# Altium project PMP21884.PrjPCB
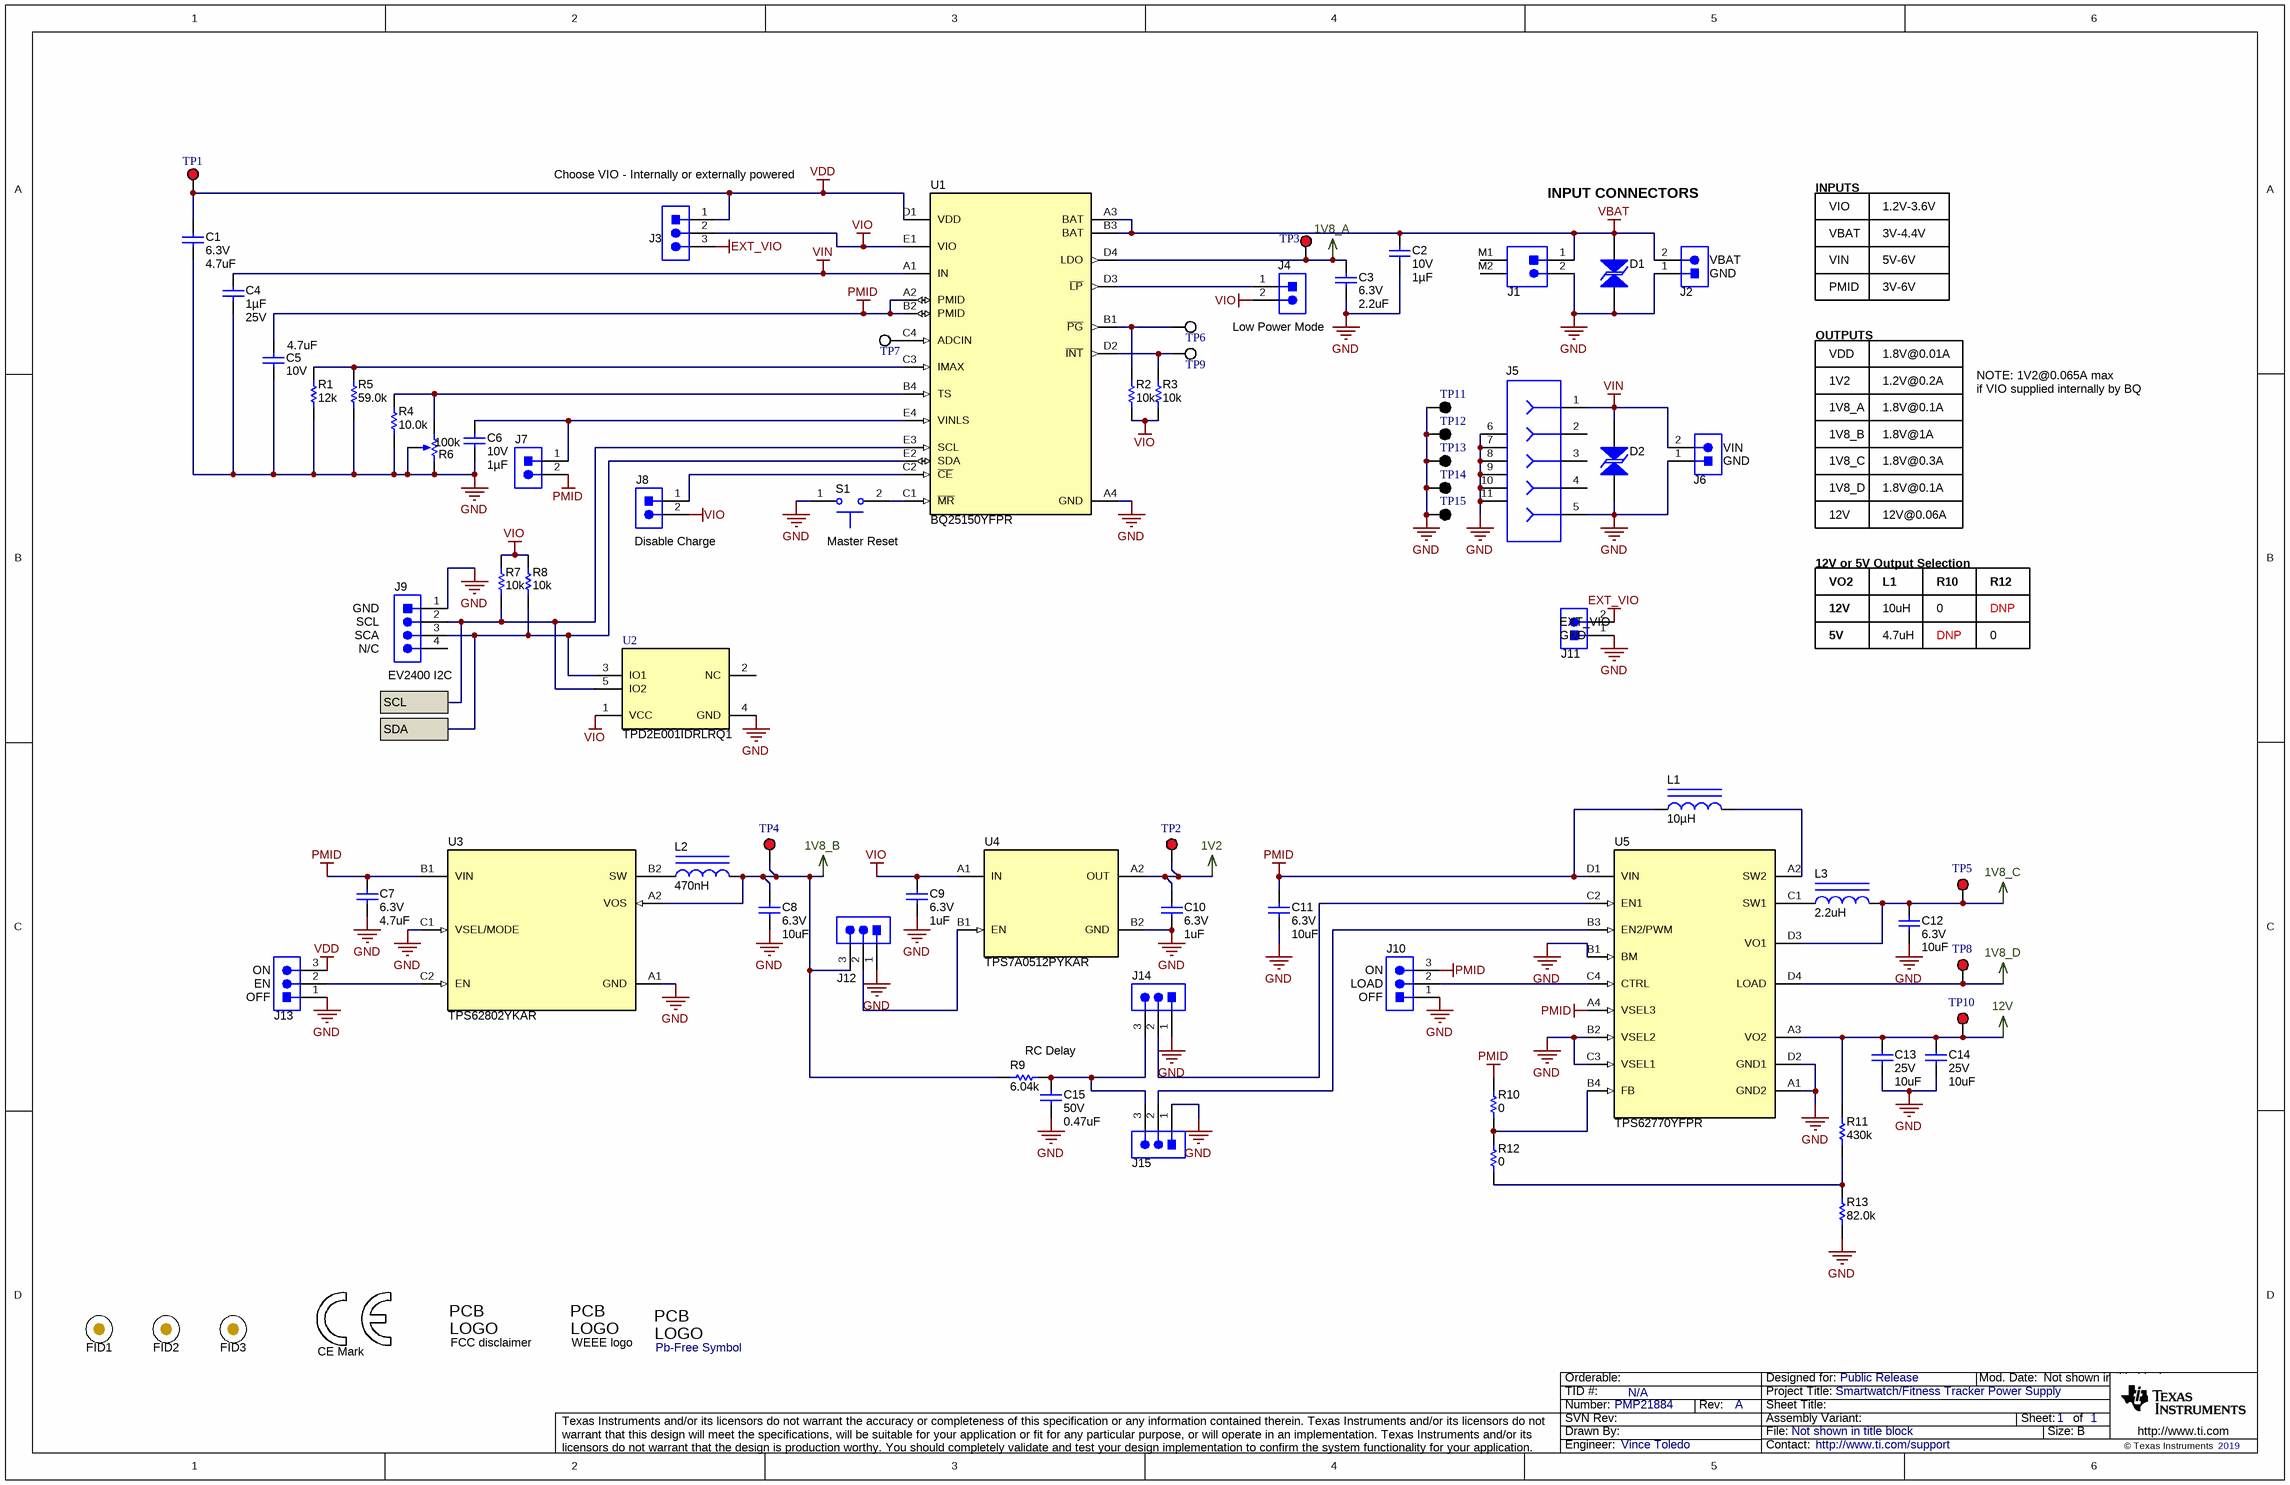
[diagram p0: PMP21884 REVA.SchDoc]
TID: N/A; TechSupport: http://www.ti.com/support; SCH_Rev: A; PRJ_Title: Smartwatch/Fitness Tracker Power Supply; PRJ_Number: PMP21884; PRJ_Engineer: Vince Toledo; PRJ_Customer: Public Release; PCB_Rev: A; PCB_Layout: Vince Toledo; CopyrightYear: 2019
1 sheet, 76 parts. Net scope: flat (ports and power ports of the same name join across sheets).
Board file: PMP21884 REVA PCB.PcbDoc

## Sheet PMP21884 REVA.SchDoc
size 431 x 279 mm; Date: Not shown in title block; ApprovedBy: Not shown in title block; CheckedBy: Not shown in title block; Author: Not shown in title block; CompanyName: Not shown in title block; Engineer: Not shown in title block; Organization: Not shown in title block; Address1: Not shown in title block; Address2: Not shown in title block; Address3: Not shown in title block; Address4: Not shown in title block; DocumentNumber: 1; Revision: Use project parameter SCH_Rev; SheetNumber: 1; SheetTotal: 1; PageSetup: Record=PageOptions¦CenterHorizontal=True¦CenterVertical=True¦PrintScale=1.00¦XCorrection=1.00¦YCorrection=1.00¦PrintKind=0¦BorderSize=5000000¦LeftOffset=0¦BottomOffset=0¦Orientation=2¦PaperLength=1000¦PaperWidth=1000¦Scale=100¦PaperSource=15¦PrintQuality=600¦MediaType=1¦DitherType=10¦PaperKind=Letter¦PrintScaleMode=1

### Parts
C1  VDC_V: 6.3V  ValueDisplayed: 4.7uF  [0201L]  (hidden comment: GRM035R60J475ME15D)
C2  VDC_V: 10V  ValueDisplayed: 1µF  [0402S]  (hidden comment: CL05A105MP5NNNC)
C3  VDC_V: 6.3V  ValueDisplayed: 2.2uF  [0201L]  (hidden comment: CL03A225MQ3CRNC)
C4  ValueDisplayed: 1µF  VDC_V: 25V  [0402S]  (hidden comment: CL05A105KA5NQNC)
C5  VDC_V: 10V  ValueDisplayed: 4.7uF  [0402S]  (hidden comment: C1005X5R1A475M050BC)
C6  VDC_V: 10V  ValueDisplayed: 1µF  [0402S]  (hidden comment: CL05A105MP5NNNC)
C7  VDC_V: 6.3V  ValueDisplayed: 4.7uF  [0201L]  (hidden comment: GRM035R60J475ME15D)
C8  VDC_V: 6.3V  ValueDisplayed: 10uF  [0402S]  (hidden comment: GRM155R60J106ME15D)
C9  VDC_V: 6.3V  ValueDisplayed: 1uF  [0201_033L]  (hidden comment: GRM033R60J105MEA2D)
C10  VDC_V: 6.3V  ValueDisplayed: 1uF  [0201_033L]  (hidden comment: GRM033R60J105MEA2D)
C11  VDC_V: 6.3V  ValueDisplayed: 10uF  [0402S]  (hidden comment: GRM155R60J106ME15D)
C12  VDC_V: 6.3V  ValueDisplayed: 10uF  [0402S]  (hidden comment: GRM155R60J106ME15D)
C13  VDC_V: 25V  ValueDisplayed: 10uF  [0603S]  (hidden comment: GRM188R61E106MA73J)
C14  VDC_V: 25V  ValueDisplayed: 10uF  [0603S]  (hidden comment: GRM188R61E106MA73J)
C15  VDC_V: 50V  ValueDisplayed: 0.47uF  [1206_190]  (hidden comment: CGA5L2X5R1H474K160AA)
D1  TPD1E6B06DPLR  [DPL0002A]  (value not drawn)
D2  TPD1E6B06DPLR  [DPL0002A]  (value not drawn)
FID1  Fiducial  [Fiducial10-20]  (value not drawn)
FID2  Fiducial  [Fiducial10-20]  (value not drawn)
FID3  Fiducial  [Fiducial10-20]  (value not drawn)
J1  S2B-PH-SM4-TB(LF)(SN)  [JST_S2B-PH-SM4-TB]  (value not drawn)
J2  PEC02SAAN  [CONN_PEC02SAAN]  (value not drawn)
J3  PEC03SAAN  [CONN_PEC03SAAN]  (value not drawn)
J4  PEC02SAAN  [CONN_PEC02SAAN]  (value not drawn)
J5  105017-0001  [CONN_105017-0001]  (value not drawn)
J6  PEC02SAAN  [CONN_PEC02SAAN]  (value not drawn)
J7  PEC02SAAN  [CONN_PEC02SAAN]  (value not drawn)
J8  PEC02SAAN  [CONN_PEC02SAAN]  (value not drawn)
J9  22/05/3041  [CONN_22-05-3041]  (value not drawn)
J10  PEC03SAAN  [CONN_PEC03SAAN]  (value not drawn)
J11  PEC02SAAN  [CONN_PEC02SAAN]  (value not drawn)
J12  PEC03SAAN  [CONN_PEC03SAAN]  (value not drawn)
J13  PEC03SAAN  [CONN_PEC03SAAN]  (value not drawn)
J14  PEC03SAAN  [CONN_PEC03SAAN]  (value not drawn)
J15  PEC03SAAN  [CONN_PEC03SAAN]  (value not drawn)
L1  ValueDisplayed: 10µH  [DFE201610E]  (hidden comment: DFE201610E-100M=P2)
L2  ValueDisplayed: 470nH  [0603L]  (hidden comment: DFE18SANR47MG0L)
L3  ValueDisplayed: 2.2uH  [0603L]  (hidden comment: LQM18PN2R2MGHD)
Logo1  CE Mark  [CE_Mark_5mm]  (no BOM)
Logo2  FCC disclaimer  [FCC_disclaimer_stacked]  (no BOM)
Logo3  WEEE logo  [WEEE_Minimum]  (no BOM)
Logo4  Pb-Free Symbol  [Pb-Free_Overlay_Small]  (no BOM)
R1  ValueDisplayed: 12k  [0201L]  (hidden comment: RC0201JR-0712KL)
R2  ValueDisplayed: 10k  [0201L]  (hidden comment: RC0201JR-0710KL)
R3  ValueDisplayed: 10k  [0201L]  (hidden comment: RC0201JR-0710KL)
R4  ValueDisplayed: 10.0k  [0201L]  (hidden comment: RC0201FR-0710KL)
R5  ValueDisplayed: 59.0k  [1206]  (hidden comment: RC1206FR-0759KL)
R6  value 100k  [TRIM_3266W]  (hidden comment: 3266W-1-104LF)
R7  ValueDisplayed: 10k  [0201L]  (hidden comment: RC0201JR-0710KL)
R8  ValueDisplayed: 10k  [0201L]  (hidden comment: RC0201JR-0710KL)
R9  ValueDisplayed: 6.04k  [1206]  (hidden comment: CRCW12066K04FKEA)
R10  ValueDisplayed: 0  [0201L]  (hidden comment: CRCW02010000Z0ED)
R11  ValueDisplayed: 430k  [0201L]  (hidden comment: RC0201JR-07430KL)
R12  ValueDisplayed: 0  [0201L]  (hidden comment: CRCW02010000Z0ED)
R13  ValueDisplayed: 82.0k  [0201L]  (hidden comment: RC0201FR-0782KL)
S1  TL1015AF160QG  [SW_TL1015AF160QG]  (value not drawn)
TP1  5010  [Keystone5010]  (value not drawn)
TP2  5010  [Keystone5010]  (value not drawn)
TP3  5010  [Keystone5010]  (value not drawn)
TP4  5010  [Keystone5010]  (value not drawn)
TP5  5010  [Keystone5010]  (value not drawn)
TP6  5012  [Keystone5012]  (value not drawn)
TP7  5012  [Keystone5012]  (value not drawn)
TP8  5010  [Keystone5010]  (value not drawn)
TP9  5012  [Keystone5012]  (value not drawn)
TP10  5010  [Keystone5010]  (value not drawn)
TP11  5011  [Keystone5011]  (value not drawn)
TP12  5011  [Keystone5011]  (value not drawn)
TP13  5011  [Keystone5011]  (value not drawn)
TP14  5011  [Keystone5011]  (value not drawn)
TP15  5011  [Keystone5011]  (value not drawn)
U1  BQ25150YFPR  [YFP0020ACAC]
U2  TPD2E001IDRLRQ1  [DRL0005A]
U3  TPS62802YKAR  [YKA0006ACAC]
U4  TPS7A0512PYKAR  [YKA0004ACAC]
U5  TPS62770YFPR  [YFP0016ACAC]

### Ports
SCL, SDA

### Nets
1V2: C10.1 TP2.1 U4.A2(OUT)
1V8_A: C3.2 TP3.1 U1.D4(LDO)
1V8_B: C8.1 J12.3 L2.2 R9.1 TP4.1 U3.A2(VOS)
1V8_C: C12.1 L3.2 TP5.1 U5.D3(VO1)
1V8_D: TP8.1 U5.D4(LOAD)
12V: C13.1 C14.1 R11.2 TP10.1 U5.A3(VO2)
EXT_VIO: J3.3 J11.2
GND: C1.2 C2.2 C3.1 C4.2 C5.2 C6.2 C7.2 C8.2 C9.2 C10.2 C11.2 C12.2 C13.2 C14.2 C15.2 D1.1 D2.1 J1.2 J2.1 J5.5 J5.6 J5.7 J5.8 J5.9 J5.10 J5.11 J6.1 J9.1 J10.1 J11.1 J12.1 J13.1 J14.1 J15.1 R1.2 R4.2 R5.1 R6.2(WIPER) R6.3(CW) R13.1 S1.1 TP11.1 TP12.1 TP13.1 TP14.1 TP15.1 U1.A4(GND) U2.4(GND) U3.A1(GND) U3.C1(VSEL/MODE) U4.B2(GND) U5.A1(GND2) U5.B1(BM) U5.B2(VSEL2) U5.C3(VSEL1) U5.D2(GND1)
PMID: C5.1 C7.1 C11.1 J7.2 J10.3 L1.1 R10.2 U1.A2(PMID) U1.B2(PMID) U3.B1(VIN) U5.A4(VSEL3) U5.D1(VIN)
VBAT: C2.1 D1.2 J1.1 J2.2 U1.A3(BAT) U1.B3(BAT)
VDD: C1.1 J3.1 J13.3 TP1.1 U1.D1(VDD)
VIN: C4.1 D2.2 J5.1 J6.2 U1.A1(IN)
VIO: C9.1 J3.2 J4.2 J8.2 R2.1 R3.1 R7.2 R8.1 U1.E1(VIO) U2.1(VCC) U4.A1(IN)
SCL: J9.2 R7.1 U1.E3(SCL) U2.5(IO2) ; port SCL
SDA: J9.3 R8.2 U1.E2(SDA) U2.3(IO1) ; port SDA
NetC6_1: C6.1 J7.1 U1.E4(VINLS)
NetC15_1: C15.1 J14.3 J15.3 R9.2
NetJ4_1: J4.1 U1.D3(~{LP})
NetJ8_1: J8.1 U1.C2(~{CE})
NetJ10_2: J10.2 U5.C4(CTRL)
NetJ12_2: J12.2 U4.B1(EN)
NetJ13_2: J13.2 U3.C2(EN)
NetJ14_2: J14.2 U5.C2(EN1)
NetJ15_2: J15.2 U5.B3(EN2/PWM)
NetL1_2: L1.2 U5.A2(SW2)
NetL2_1: L2.1 U3.B2(SW)
NetL3_1: L3.1 U5.C1(SW1)
NetR1_1: R1.1 R5.2 U1.C3(IMAX)
NetR2_2: R2.2 TP6.1 U1.B1(~{PG})
NetR3_2: R3.2 TP9.1 U1.D2(~{INT})
NetR4_1: R4.1 R6.1(CCW) U1.B4(TS)
NetR10_1: R10.1 R12.2 U5.B4(FB)
NetR11_1: R11.1 R12.1 R13.2
NetS1_2: S1.2 U1.C1(~{MR})
NetTP7_1: TP7.1 U1.C4(ADCIN)

Not connected (* = marked no-connect by the designer): J1 M1 M2; J5 2 3 4; J9 4; U2 2(NC)

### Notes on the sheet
- (near J3) Choose VIO - Internally or externally powered
- INPUT CONNECTORS
- INPUTS
- VBAT
- VIO
- 3V-4.4V
- 1.2V-3.6V
- (near J2) VBAT
- (near J2) GND
- VIN
- PMID
- 5V-6V
- 3V-6V
- (near J4) Low Power Mode
- OUTPUTS
- VDD
- 1.8V@0.01A
- NOTE: 1V2@0.065A max
- 1V2
- 1V8_A
- 1V8_B
- 1.2V@0.2A
- 1.8V@0.1A
- 1.8V@1A
- if VIO supplied internally by BQ
- (near J6) VIN
- (near J6) GND
- 1V8_C
- 1V8_D
- 1.8V@0.3A
- (near J8) Disable Charge
- Master Reset
- 12V or 5V Output Selection
- 12V
- 12V@0.06A
- (near J9) GND
- (near J9) SCL
- (near J9) SCA
- (near J11) EXT_VIO
- (near J11) GND
- VO2
- 5V
- L1
- 10uH
- 4.7uH
- R10
- 0
- DNP
- R12
- (near J9) N/C
- (near J9) EV2400 I2C
- (near J13) ON
- (near J10) ON
- (near J13) EN
- (near J13) OFF
- (near J10) LOAD
- (near J10) OFF
- RC Delay

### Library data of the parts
C1 C7 = CMP-0009780-1: CAP, CERM, 4.7 uF, 6.3 V, +/- 20%, X5R, 0201; Manufacturer: MuRata; TaMin_C: -55°C; Polarized: N; SizeAreaWB_mm2: 2.08; Value1: Unknown; U/M: EA; Value: 4.7uF; TaMax_C: 85°C; SizeZ_mm: 0.26; SizeX_mm: 0.6; SizeY_mm: 0.3; Cap_Case: 0201; SizeArea_mm2: 0.18; Cap_F: 4.7µF; AEC Category: Q200
C2 C6 = CMP-0085849-1: CAP, CERM, 1 µF, 10 V,+/- 20%, X5R, 0402; Manufacturer: Samsung Electro-Mechanics; U/M: EA; TaMin_C: -55°C; Value: 1uF; Cap_Case: 0402; SizeAreaWB_mm2: 3; SizeZ_mm: 0.6; AEC Category: Q200; SizeY_mm: 0.5; TaMax_C: 85°C; AEC Qualified: N; SizeX_mm: 1
C3 = CMP-0009657-3: CAP, CERM, 2.2 uF, 6.3 V, +/- 20%, X5R, 0201; Manufacturer: Samsung Electro-Mechanics; TaMin_C: -55°C; Polarized: N; SizeAreaWB_mm2: 2.08; Value1: Unknown; U/M: EA; Value: 2.2uF; TaMax_C: 85°C; SizeZ_mm: 0.26; SizeX_mm: 0.6; SizeY_mm: 0.3; Cap_Case: 0201; SizeArea_mm2: 0.18; Cap_F: 2.2µF; AEC Category: Q200
C4 = CMP-0085848-1: CAP, CERM, 1 µF, 25 V,+/- 10%, X5R, 0402; Manufacturer: Samsung Electro-Mechanics; SizeZ_mm: 0.6; AEC Category: Q200; Value: 1uF; SizeArea_mm2: 0.5; TaMax_C: 85°C; TaMin_C: -55°C; SizeX_mm: 1; Cap_Case: 0402; AEC Qualified: N; U/M: EA; SizeAreaWB_mm2: 3
C5 = CMP-0006269-2: CAP, CERM, 4.7 uF, 10 V, +/- 20%, X5R, 0402; Manufacturer: TDK; TaMin_C: -55°C; Polarized: N; SizeAreaWB_mm2: 3; Value1: Unknown; U/M: EA; Value: 4.7uF; TaMax_C: 85°C; SizeZ_mm: 0.6; SizeX_mm: 1; SizeY_mm: 0.5; Cap_Case: 0402; Cap_F: 4.7µF; AEC Category: Q200
C8 C11 C12 = CMP-0006534-2: CAP, CERM, 10 uF, 6.3 V, +/- 20%, X5R, 0402; Manufacturer: MuRata; TaMin_C: -55°C; Polarized: N; SizeAreaWB_mm2: 3; Value1: Unknown; U/M: EA; Value: 10uF; TaMax_C: 85°C; SizeZ_mm: 0.6; SizeX_mm: 1; SizeY_mm: 0.5; Cap_Case: 0402; Cap_F: 10µF; AEC Category: Q200
C9 C10 = CMP-0009692-3: CAP, CERM, 1 uF, 6.3 V, +/- 20%, X5R, 0201; Manufacturer: MuRata; TaMin_C: -55°C; Polarized: N; SizeAreaWB_mm2: 2.08; Value1: Unknown; U/M: EA; Value: 1uF; TaMax_C: 85°C; SizeZ_mm: 0.33; SizeX_mm: 0.6; SizeY_mm: 0.3; Cap_Case: 0201; SizeArea_mm2: 0.18; Cap_F: 1µF; AEC Category: Q200
C13 C14 = CMP-0007344-5: CAP, CERM, 10 uF, 25 V, +/- 20%, X5R, 0603; Manufacturer: MuRata; TaMin_C: -55°C; Polarized: N; SizeAreaWB_mm2: 4.68; Value1: Unknown; U/M: EA; Value: 10uF; TaMax_C: 85°C; SizeZ_mm: 1; SizeX_mm: 1.6; SizeY_mm: 0.8; Cap_Case: 0603; SizeArea_mm2: 1.28; Cap_F: 10µF; AEC Category: Q200
C15 = CMP-0008774-2: CAP, CERM, 0.47 uF, 50 V, +/- 10%, X5R, AEC-Q200 Grade 3, 1206_190; Manufacturer: TDK; SizeAreaWB_mm2: 10.92; Value1: Unknown; U/M: EA; Value: 0.47uF; TaMax_C: 85°C; SizeZ_mm: 1.9; SizeX_mm: 3.2; SizeY_mm: 1.6; Cap_Case: 1206; SizeArea_mm2: 5.12; AEC Qualified: Y; Cap_F: 470nF; AEC Grade: 3; AEC Category: Q200; TaMin_C: -55°C; Polarized: N
D1 D2 = CMP-0750037-1: Single-Channel ESD in 0201 Package With 6pF Capacitance and 6V Breakdown, DPL0002A (X2SON-2); Alternate Manufacturer: Texas Instruments; Alternate PartNumber: TPD1E6B06DPLT; AEC Category: Q200; CompType: IC; SizeAreaWB_mm2: 2.08; SizeX_mm: 0.6; SizeY_mm: 0.3; SizeArea_mm2: 0.18; Rating: Catalog; AEC Qualified: N; SizeZ_mm: 0.32
FID1-FID3 = CMP-0077181-1: Fiducial mark.  There is nothing to buy or mount.
J1 = CMP-0074984-1: Header (shrouded), 2mm, 2x1, R/A, SMT; Manufacturer: JST Manufacturing; CT: False
J2 J4 J6-J8 J11 = CMP-0002337-1: Header, 100mil, 2x1, Tin, TH; Manufacturer: Sullins Connector Solutions; CNHeader: TRUE; Current_A: 3A; Green_Lifecycle: Not Set; Shrouded: N; Gender: Male; Green_REACh: Incomplete; Voltage_V: 1.8kV; Row_Count: 1; Pitch_mm: 2.54; CT: FALSE; Cert_UL: Y
J3 J10 J12-J15 = CMP-0002338-1: Header, 100mil, 3x1, Tin, TH; Manufacturer: Sullins Connector Solutions; CNHeader: TRUE; Current_A: 3A; Green_Lifecycle: Not Set; Shrouded: N; Gender: Male; Green_REACh: Incomplete; Voltage_V: 1.8kV; Row_Count: 1; Pitch_mm: 2.54; CT: FALSE; Cert_UL: Y
J5 = CMP-0055293-1: Connector, Receptacle, Micro-USB Type B, R/A, Bottom Mount SMT; Manufacturer: Molex; CNHeader: FALSE; Green_Lifecycle: Active; Gender: Female; Green_REACh: Passed; CompType: USB; CT: TRUE
J9 = CMP-0055187-1: Header (friction lock), 100mil, 4x1, R/A, TH; Manufacturer: Molex; CNHeader: FALSE; Green_Lifecycle: Active; Green_REACh: Passed
L1 = CMP-0080880-2: Inductor, Shielded, Metal Composite, 10 µH, 0.65 A, 0.78 ohm, SMD; Manufacturer: MuRata; Isat: 1A @ 30% inductance drop; Irms: 0.65A @ 40C rise; SizeAreaWB_mm2: 7.8; DCR_ohm: 0.78; Value: 10uH; Imax_A: 650mA; SizeZ_mm: 1; SizeX_mm: 2; SizeY_mm: 1.6; Value2: 0.65A; SizeArea_mm2: 3.2; AEC Qualified: N; AEC Category: Q200
L2 = CMP-0078483-1: Inductor, Shielded, Metal Composite, 470 nH, 2.6 A, 0.054 ohm, SMD; Manufacturer: MuRata; Isat: 3.6A @ 30% inductance drop; Irms: 2.6A @ 40C rise; SizeAreaWB_mm2: 4.68; DCR_ohm: 0.054; Value: 470nH; Imax_A: 2.6A; SizeZ_mm: 1; SizeX_mm: 1.6; SizeY_mm: 0.8; SizeArea_mm2: 1.28; AEC Qualified: N; AEC Category: Q200
L3 = CMP-0058736-1: Inductor, Ferrite, 2.2 uH, 0.25 A, 0.2 ohm, SMD; Manufacturer: MuRata; Isat: 0.25A @ 30% inductance drop; Irms: 1.05A @ 40C rise; Green_Lifecycle: Active; SizeAreaWB_mm2: 4.68; DCR_ohm: 0.2; Green_REACh: Passed; Value1: 0.2 ohm; Value: 2.2uH; Imax_A: 250mA; SizeZ_mm: 1; SizeX_mm: 1.6; SizeY_mm: 0.8; Value2: 0.25A; SizeArea_mm2: 1.28; Ind_H: 2.2µH; AEC Qualified: N; AEC Category: Q200
Logo1 = CMP-0074844-1: SymbolCreator: a0412235
Logo2 = CMP-0074847-1: FCC_disclaimer; Library Reference: Logo
Logo3 = CMP-0074769-1
Logo4 = CMP-0074839-1: SymbolCreator: a0412235
R1 = CMP-0027028-1: RES, 12 k, 5%, 0.05 W, 0201; Manufacturer: Yageo America; Power_W: 50mW; TempCo: 200 ppm/C; Value_Code: 12k0; U/M: EA; Value: 12k; EIA_Code: E24; SizeX_mm: 0.6; SizeY_mm: 0.3; SizeZ_mm: 0.26; Value2: 0.05W; SizeArea_mm2: 0.18; AEC Qualified: N; VDC_V: 25V; AEC Category: Q200
R2 R3 R7 R8 = CMP-0027019-1: RES, 10 k, 5%, 0.05 W, 0201; Manufacturer: Yageo America; Power_W: 50mW; TempCo: 200 ppm/C; Value_Code: 10k0; U/M: EA; Value: 10k; EIA_Code: E24; SizeX_mm: 0.6; SizeY_mm: 0.3; SizeZ_mm: 0.26; Value2: 0.05W; SizeArea_mm2: 0.18; AEC Qualified: N; VDC_V: 25V; AEC Category: Q200
R4 = CMP-0027304-2: RES, 10.0 k, 1%, 0.05 W, 0201; Manufacturer: Yageo America; Power_W: 50mW; TempCo: 200 ppm/C; Value_Code: 10k0; U/M: EA; Value: 10.0k; EIA_Code: E96; Res_ohm: 10k; SizeX_mm: 0.6; SizeY_mm: 0.3; SizeZ_mm: 0.26; Value2: 0.05W; SizeArea_mm2: 0.18; AEC Qualified: N; VDC_V: 25V; AEC Category: Q200
R5 = CMP-0018387-2: RES, 59.0 k, 1%, 0.25 W, 1206; Manufacturer: Yageo America; Power_W: 250mW; TempCo: 100 ppm/C; Value_Code: 59k0; U/M: EA; Value: 59.0k; EIA_Code: E96; Res_ohm: 59k; SizeX_mm: 3.2; SizeY_mm: 1.6; SizeZ_mm: 1.35; Value2: 0.25W; SizeArea_mm2: 5.12; VDC_V: 200V; AEC Category: Q200
R6 = CMP-0002070-1: Trimmer, 100k ohm, 0.25W, TH; Manufacturer: Bourns
R9 = CMP-0017127-3: RES, 6.04 k, 1%, 0.25 W, AEC-Q200 Grade 0, 1206; Manufacturer: Vishay-Dale; Power_W: 250mW; TempCo: 100 ppm/C; Value_Code: 6k04; Value: 6.04k; EIA_Code: E96; SizeX_mm: 3.2; SizeY_mm: 1.6; SizeZ_mm: 1.35; Value2: 0.25W; SizeArea_mm2: 5.12; AEC Qualified: Y; VDC_V: 200V; AEC Category: Q200; AEC Grade: 0
R10 R12 = CMP-0027008-4: RES, 0, 5%, 0.05 W, 0201; Manufacturer: Vishay-Dale; Power_W: 50mW; TempCo: ppm/C; Value_Code: 0000; Value: 0; EIA_Code: E24; SizeX_mm: 0.6; SizeY_mm: 0.3; SizeZ_mm: 0.26; Value2: 0.05W; SizeArea_mm2: 0.18; AEC Qualified: N; AEC Category: Q200
R11 = CMP-0027122-1: RES, 430 k, 5%, 0.05 W, 0201; Manufacturer: Yageo America; Power_W: 50mW; TempCo: 200 ppm/C; U/M: EA; Value: 430k; EIA_Code: E24; SizeX_mm: 0.6; SizeY_mm: 0.3; SizeZ_mm: 0.26; Value2: 0.05W; SizeArea_mm2: 0.18; AEC Qualified: N; VDC_V: 25V; AEC Category: Q200
R13 = CMP-0027892-1: RES, 82.0 k, 1%, 0.05 W, 0201; Manufacturer: Yageo America; Power_W: 50mW; TempCo: 200 ppm/C; Value_Code: 82k0; U/M: EA; Value: 82.0k; Res_ohm: 82k; SizeX_mm: 0.6; SizeY_mm: 0.3; SizeZ_mm: 0.26; Value2: 0.05W; SizeArea_mm2: 0.18; AEC Qualified: N; VDC_V: 25V; AEC Category: Q200
S1 = CMP-0002143-3: Switch, Tactile, SPST-NO, 0.05A, 12V, SMT; Manufacturer: E-Switch; CurrentRating_mA: 50A; PositionCount: 1; SwitchFunction: Off-Mom
TP1-TP5 TP8 TP10 = CMP-0055147-1: Test Point, Multipurpose, Red, TH; Manufacturer: Keystone; CNHeader: FALSE; Green_Lifecycle: Active; Green_REACh: Passed; ContactFinish: Silver; CT: TRUE
TP6 TP7 TP9 = CMP-0055149-1: Test Point, Multipurpose, White, TH; Manufacturer: Keystone; CNHeader: FALSE; Green_Lifecycle: Active; Green_REACh: Passed; ContactFinish: Silver; CT: TRUE
TP11-TP15 = CMP-0055148-1: Test Point, Multipurpose, Black, TH; Manufacturer: Keystone; CNHeader: FALSE; Green_Lifecycle: Active; Green_REACh: Passed; ContactFinish: Silver; CT: TRUE
U1 = CMP-0077167-2: BQ25150YFP, YFP0020ACAC (DSBGA-20); Alternate PartNumber: BQ25150YFPT; Alternate Manufacturer: Texas Instruments; SizeX_mm: 1.615; CompType: IC; SizeAreaWB_mm2: 7.884225; SizeZ_mm: 0.5; SizeY_mm: 2.015; U/M: EA; SizeArea_mm2: 3.254225
U2 = CMP-0043127-2: Automotive Catalog Low-Capacitance + / - 15 kV ESD-Protection Array for High-Speed Data Inter, 2 Channels, -40 to +85 degC, 5-pin SOT (DRL), Green (RoHS & no Sb/Br); Manufacturer: Texas Instruments; IO Leakage Current(nA): 1; IO Capacitance(Typ)(pF): 1.5; USB High Speed: TRUE; SubFamily: ESD Solution; Breakdown Voltage(Min)(V): 11; IEC 61000-4-2 Air-Gap(+/- kV): 15; IEC 61000-4-2 Contact(+/- kV): 8
U3 = CMP-0077660-3: Tiny High Frequency Ultra-low Iq Step-Down Converter, YKA0006ACAC (DSBGA-6); Alternate PartNumber: TPS62802YKAT; Alternate Manufacturer: Texas Instruments; SizeAreaWB_mm2: 3.6366; SizeZ_mm: 0.4; SizeX_mm: 0.74; SizeY_mm: 1.09; SizeArea_mm2: 0.8066; CompType: IC; AEC Qualified: N; AEC Category: Q200
U4 = CMP-0100015-2: 1µA, ultra-low Iq, 200mA low-dropout (LDO) regulator in a small-size package, YKA0004ACAC (DSBGA-4); Alternate Manufacturer: Texas Instruments; SizeAreaWB_mm2: 2.930944; SizeZ_mm: 0.4; SizeX_mm: 0.712; SizeArea_mm2: 0.506944; CompType: IC; AEC Qualified: N; AEC Category: Q200; Rating: Catalog
U5 = CMP-0074186-1: Tiny Single-chip Dual Solution with 360nA Iq Buck and up to 15V Boost in WCSP, YFP0016ACAC (DSBGA-16); Alternate PartNumber: TPS62770YFPT; Alternate Manufacturer: Texas Instruments; Green_Lifecycle: Active; SizeAreaWB_mm2: 6.666724; Green_REACh: Passed; U/M: EA; SizeZ_mm: 0.5; SizeX_mm: 1.582; SizeArea_mm2: 2.502724; CompType: IC

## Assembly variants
001: not fitted R2 R3 R7 R8 R12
